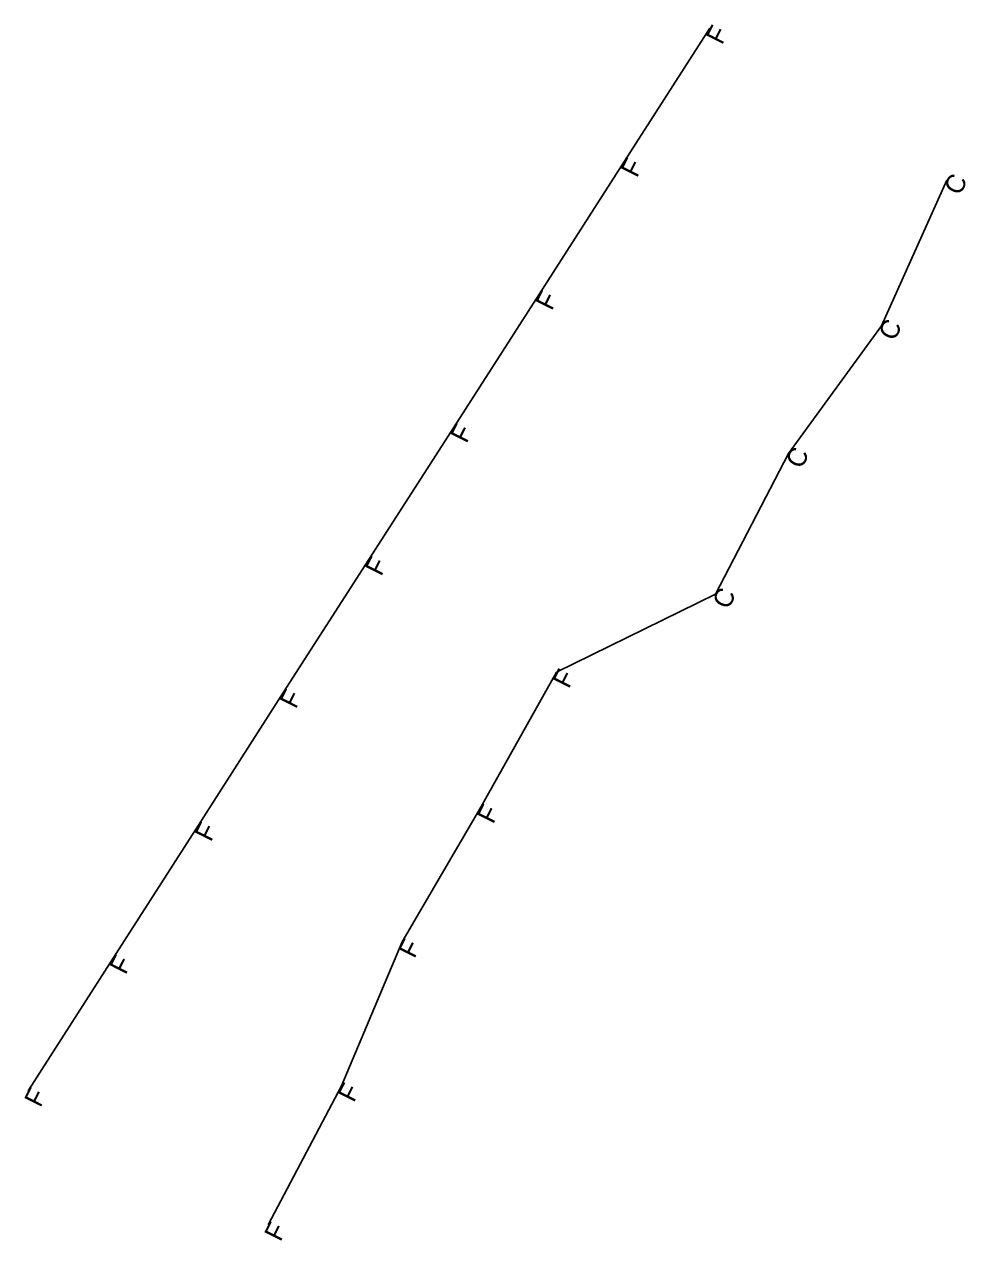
# Model space of a CAD drawing. Extents: x -26 to 2348767, y -10 to 845205.
# Drawn here: x 2348468.9 to 2348767.1, y 844819.6 to 845205 of the extents above; entities that cross this region are included whole.
import ezdxf

# ---------------------------------------------------------------- set-up
doc = ezdxf.new("R2010")
doc.units = 0
for name, color, linetype in [('Prop SS Cut Line', 7, 'Continuous'), ('Prop SS Fill Line', 7, 'Continuous'), ('Prop SS Fill Text', 7, 'Continuous'), ('Prop SS Transition Line', 7, 'Continuous')]:
    doc.layers.add(name, color=color, linetype=linetype)

msp = doc.modelspace()

# ---------------------------------------------------------------- linework, layer by layer
at = {"layer": 'Prop SS Cut Line'}
for p, q in [((2348740.4, 845109.55), (2348761.13, 845155.65)), ((2348710.98, 845069.01), (2348740.4, 845109.55)), ((2348687.81, 845024.48), (2348710.98, 845069.01))]:
    msp.add_line(p, q, dxfattribs=at)
at = {"layer": 'Prop SS Fill Line'}
for p, q in [((2348659.02, 845161.73), (2348686.01, 845203.82)), ((2348632.03, 845119.65), (2348659.02, 845161.73)), ((2348605.03, 845077.56), (2348632.03, 845119.65)), ((2348578.04, 845035.47), (2348605.03, 845077.56)), ((2348551, 844993.42), (2348578.04, 845035.47)), ((2348613.47, 844956.97), (2348637.46, 844999.82)), ((2348524.06, 844951.29), (2348551, 844993.42)), ((2348588.55, 844914.35), (2348613.47, 844956.97)), ((2348497.07, 844909.2), (2348524.06, 844951.29)), ((2348569.39, 844868.69), (2348588.55, 844914.35)), ((2348470.07, 844867.11), (2348497.07, 844909.2)), ((2348546.09, 844824.61), (2348569.39, 844868.69))]:
    msp.add_line(p, q, dxfattribs=at)
at = {"layer": 'Prop SS Transition Line'}
msp.add_line((2348637.46, 844999.82), (2348687.81, 845024.48), dxfattribs=at)

# ---------------------------------------------------------------- texts
at = {"layer": 'Prop SS Fill Text'}
for s, p in [('F', (2348689.89, 845198.26)), ('F', (2348662.9, 845156.17)), ('C', (2348765.23, 845150.51)), ('F', (2348635.91, 845114.08)), ('C', (2348744.49, 845104.41)), ('F', (2348608.92, 845072)), ('C', (2348715.08, 845063.87)), ('F', (2348581.93, 845029.91)), ('C', (2348691.9, 845019.34)), ('F', (2348641.34, 844994.26)), ('F', (2348554.88, 844987.85)), ('F', (2348617.35, 844951.41)), ('F', (2348527.94, 844945.73)), ('F', (2348592.43, 844908.79)), ('F', (2348500.96, 844903.64)), ('F', (2348473.96, 844861.55)), ('F', (2348573.27, 844863.13)), ('F', (2348549.98, 844819.05))]:
    msp.add_text(s, height=6, rotation=63.3281, dxfattribs=at).set_placement(p)

doc.saveas('drawing.dxf')
